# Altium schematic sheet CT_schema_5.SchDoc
size 479 x 328 mm
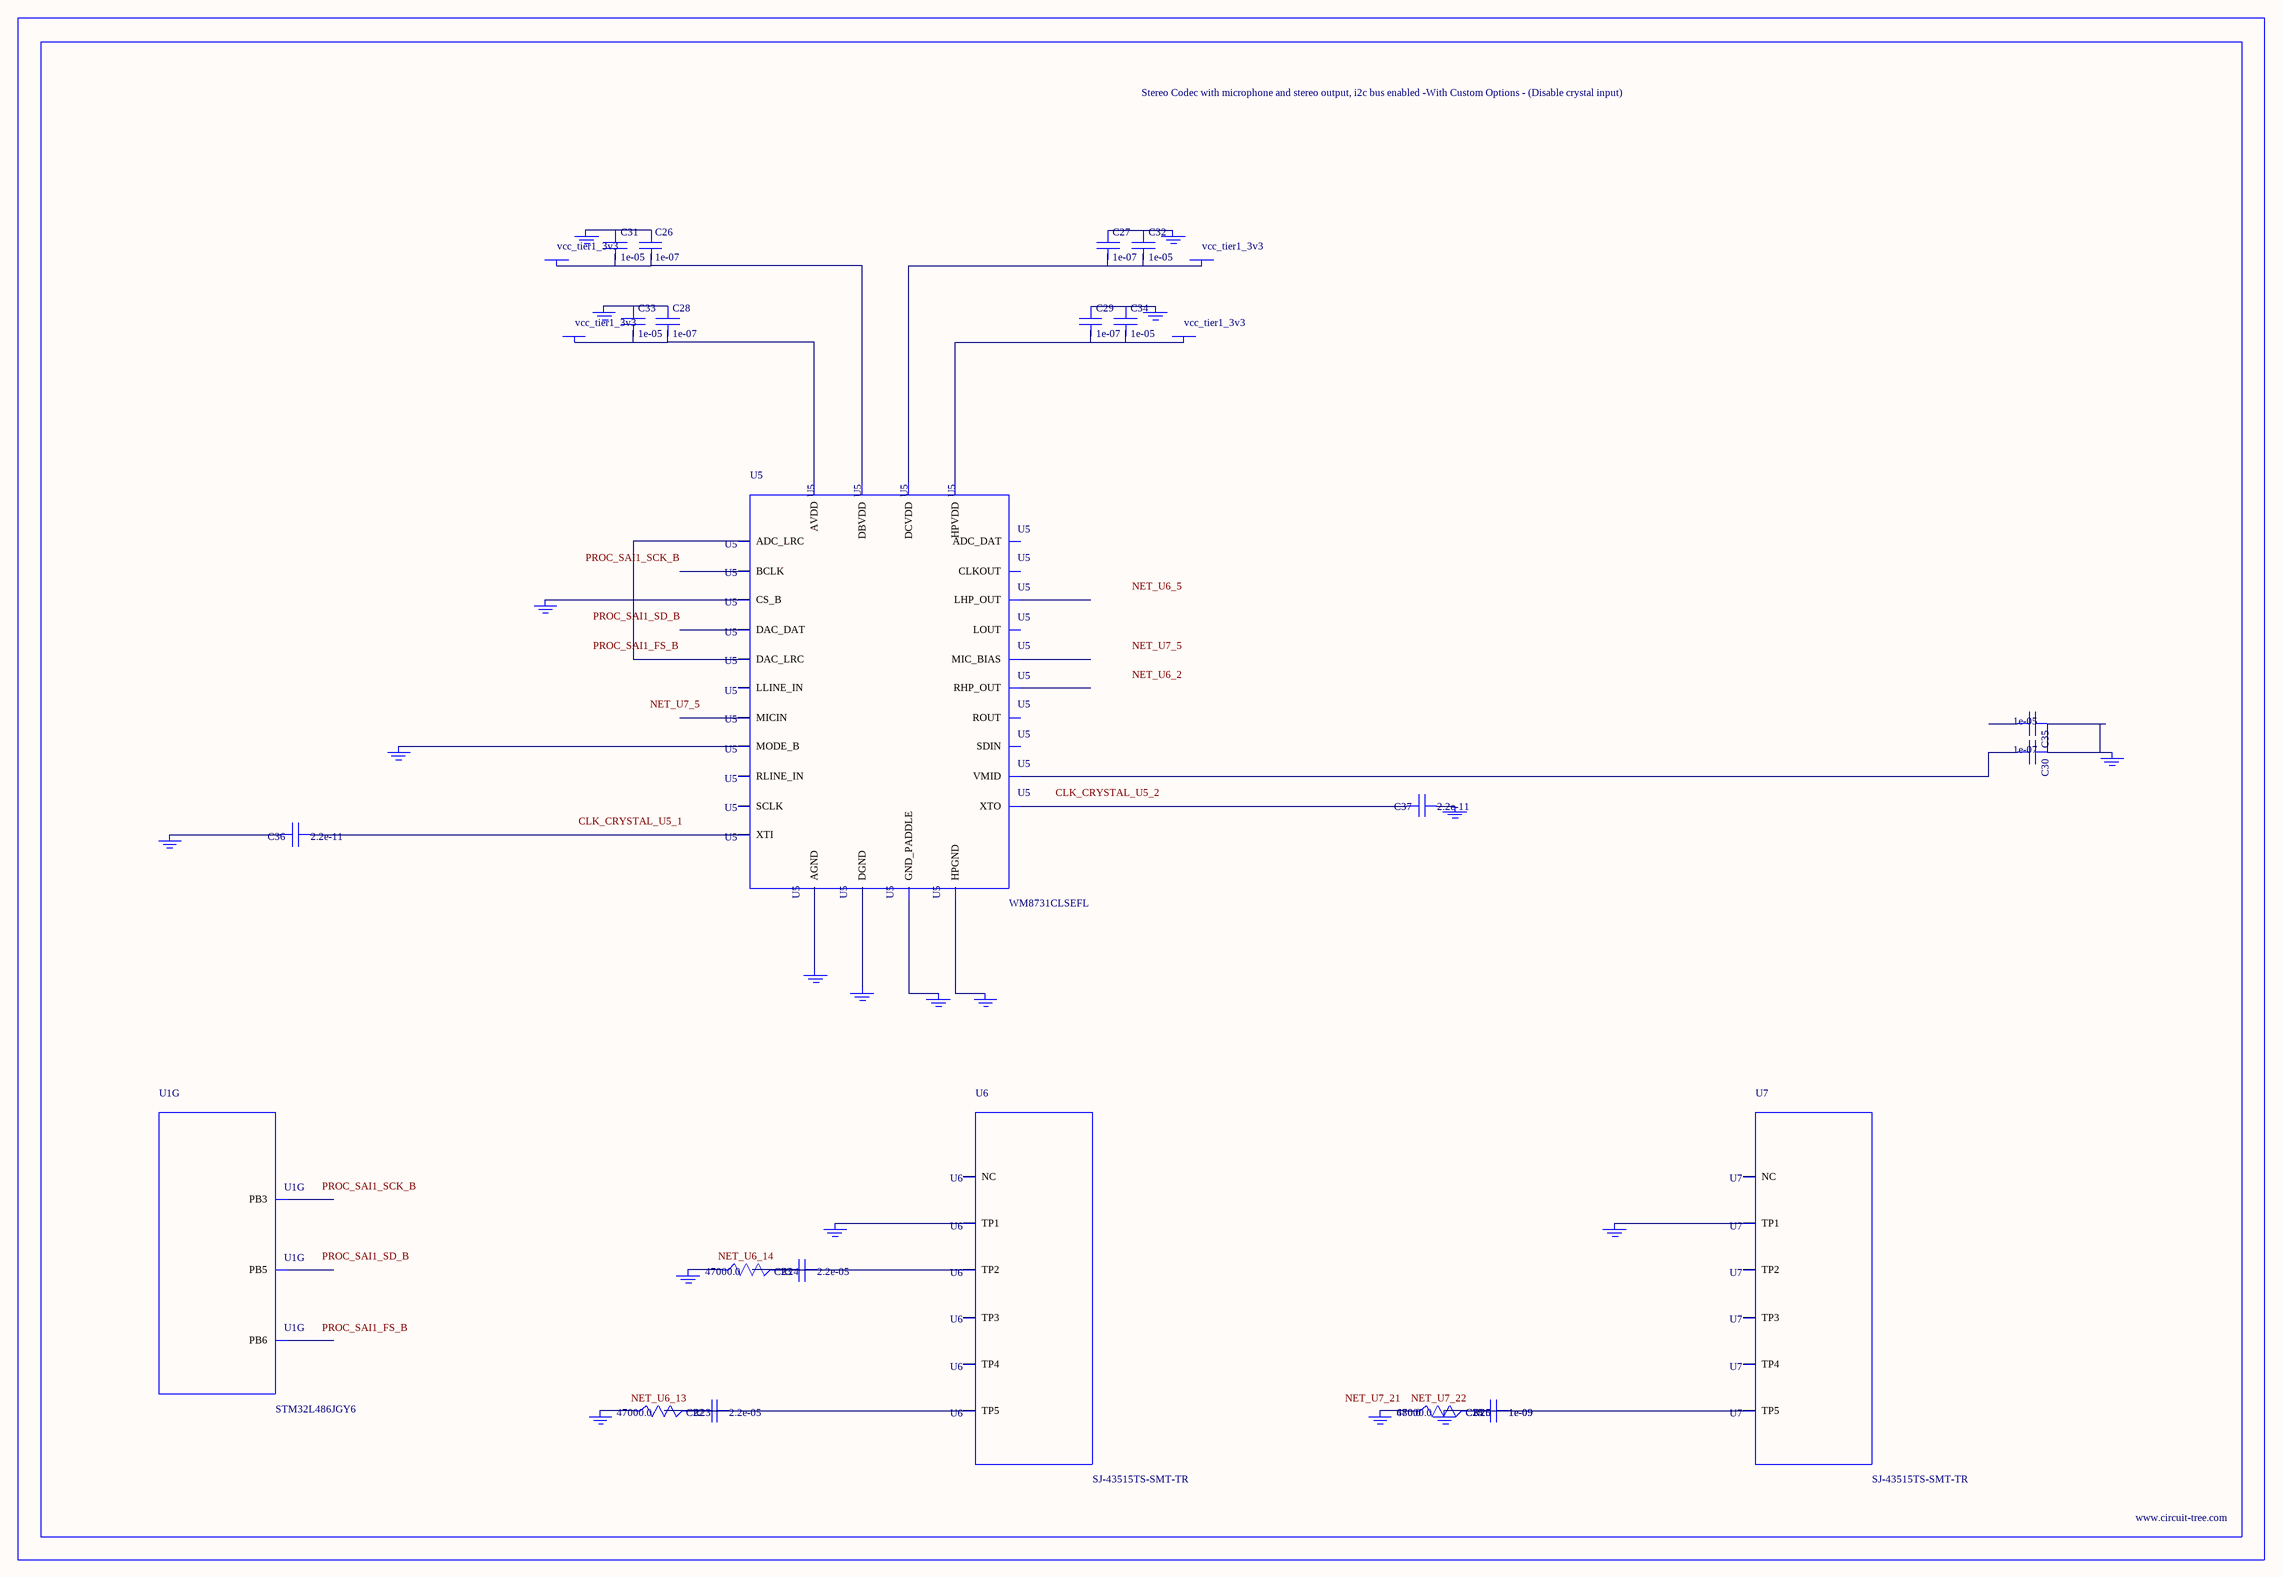
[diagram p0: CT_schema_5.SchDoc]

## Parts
BORDER4  (no value)
C22  2.2e-05  [C1210]
C23  2.2e-05  [C1210]
C24  1e-09  [C0402]
C25  1e-09  [C0402]
C26  1e-07  [C0402]
C27  1e-07  [C0402]
C28  1e-07  [C0402]
C29  1e-07  [C0402]
C30  1e-07  [C0402]
C31  1e-05  [C0805]
C32  1e-05  [C0805]
C33  1e-05  [C0805]
C34  1e-05  [C0805]
C35  1e-05  [C0805]
C36  2.2e-11  [C0402]
C37  2.2e-11  [C0402]
GND_INSTANCE_4_0  (no value)
GND_INSTANCE_4_1  (no value)
GND_INSTANCE_4_2  (no value)
GND_INSTANCE_4_3  (no value)
GND_INSTANCE_4_4  (no value)
GND_INSTANCE_4_5  (no value)
GND_INSTANCE_4_6  (no value)
GND_INSTANCE_4_7  (no value)
GND_INSTANCE_4_8  (no value)
GND_INSTANCE_4_9  (no value)
GND_INSTANCE_4_10  (no value)
GND_INSTANCE_4_11  (no value)
GND_INSTANCE_4_12  (no value)
GND_INSTANCE_4_13  (no value)
GND_INSTANCE_4_14  (no value)
GND_INSTANCE_4_15  (no value)
GND_INSTANCE_4_16  (no value)
GND_INSTANCE_4_17  (no value)
GND_INSTANCE_4_18  (no value)
POWER_INSTANCE_4_0  vcc_tier1_3v3
POWER_INSTANCE_4_1  vcc_tier1_3v3
POWER_INSTANCE_4_2  vcc_tier1_3v3
POWER_INSTANCE_4_3  vcc_tier1_3v3
R23  47000.0  [R0603]
R24  47000.0  [R0603]
R25  47000.0  [R0603]
R26  680.0  [R0603]
U1  STM32L486JGY6  [WLCSP72]  (part G of 7)
U5  WM8731CLSEFL  [QFN-28]
U6  SJ-43515TS-SMT-TR  [SJ-43515TS-SMT-TR]
U7  SJ-43515TS-SMT-TR  [SJ-43515TS-SMT-TR]

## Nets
NetC22_1: C22.1 C22.2 R23.2 U6.5(TP5)
NetC23_1: C23.1 C23.2 R24.2 U6.2(TP2)
NetC24_1: C24.1 C24.2 C25.1 C25.2 GND_INSTANCE_4_18.0(GND) R25.2 R26.2 U7.5(TP5)
NetC26_1: C26.1 C31.1 GND_INSTANCE_4_3.0(GND)
NetC26_2: C26.2 C31.2 POWER_INSTANCE_4_1.0(PWR) U5.5(DBVDD)
NetC27_1: C27.1 C32.1 GND_INSTANCE_4_2.0(GND)
NetC27_2: C27.2 C32.2 POWER_INSTANCE_4_0.0(PWR) U5.3(DCVDD)
NetC28_1: C28.1 C33.1 GND_INSTANCE_4_6.0(GND)
NetC28_2: C28.2 C33.2 POWER_INSTANCE_4_3.0(PWR) U5.18(AVDD)
NetC29_1: C29.1 C34.1 GND_INSTANCE_4_4.0(GND)
NetC29_2: C29.2 C34.2 POWER_INSTANCE_4_2.0(PWR) U5.12(HPVDD)
NetC30_1: C30.1 C35.1 GND_INSTANCE_4_7.0(GND)
NetC30_2: C30.2 U5.20(VMID)
NetC36_1: C36.1 U5.1(XTI)
NetC36_2: C36.2 GND_INSTANCE_4_0.0(GND)
NetC37_1: C37.1 GND_INSTANCE_4_1.0(GND)
NetC37_2: C37.2 U5.2(XTO)
NetGND_INSTANCE_4_5_0: GND_INSTANCE_4_5.0(GND) U5.15(HPGND)
NetGND_INSTANCE_4_8_0: GND_INSTANCE_4_8.0(GND) U5.25(MODE_B)
NetGND_INSTANCE_4_9_0: GND_INSTANCE_4_9.0(GND) U5.26(CS_B)
NetGND_INSTANCE_4_10_0: GND_INSTANCE_4_10.0(GND) U5.29(GND_PADDLE)
NetGND_INSTANCE_4_11_0: GND_INSTANCE_4_11.0(GND) U5.4(DGND)
NetGND_INSTANCE_4_12_0: GND_INSTANCE_4_12.0(GND) U5.19(AGND)
NetGND_INSTANCE_4_13_0: GND_INSTANCE_4_13.0(GND) U6.1(TP1)
NetGND_INSTANCE_4_14_0: GND_INSTANCE_4_14.0(GND) R24.1
NetGND_INSTANCE_4_15_0: GND_INSTANCE_4_15.0(GND) R23.1
NetGND_INSTANCE_4_16_0: GND_INSTANCE_4_16.0(GND) U7.1(TP1)
NetGND_INSTANCE_4_17_0: GND_INSTANCE_4_17.0(GND) R25.1 R26.1
NetU5_9: U5.9(DAC_LRC) U5.11(ADC_LRC)

Not connected (* = marked no-connect by the designer): C35 2; U1 A6(PB3) B7(PB6) C7(PB5); U5 6(CLKOUT) 7(BCLK) 8(DAC_DAT) 10(ADC_DAT) 13(LHP_OUT) 14(RHP_OUT) 16(LOUT) 17(ROUT) 21(MIC_BIAS) 22(MICIN) 23(RLINE_IN) 24(LLINE_IN) 27(SDIN) 28(SCLK); U6 3(TP3) 4(TP4) 6(NC); U7 2(TP2) 3(TP3) 4(TP4) 6(NC)

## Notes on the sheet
- Labels drawn without touching a wire or pin: CLK_CRYSTAL_U5_1, CLK_CRYSTAL_U5_2, NET_U6_2, NET_U6_5, NET_U6_13, NET_U6_14, NET_U7_5, NET_U7_21, NET_U7_22, PROC_SAI1_FS_B, PROC_SAI1_SCK_B, PROC_SAI1_SD_B

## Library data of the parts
BORDER4 = BORDER_PAGE4
C22 C23 = C1210C224K5RACTU
C24 C25 = C0402C102K3RAC
C26-C30 = C0402C104K3RACTU
C31-C35 = C0805C106K8RACTU
C36 C37 = C0402C220K3RAC
GND_INSTANCE_4_0-GND_INSTANCE_4_18 = GND
POWER_INSTANCE_4_0-POWER_INSTANCE_4_3 = PWR
R23-R25 = RC0603JR-0747KL
R26 = RC0603JR-07680RL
